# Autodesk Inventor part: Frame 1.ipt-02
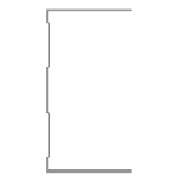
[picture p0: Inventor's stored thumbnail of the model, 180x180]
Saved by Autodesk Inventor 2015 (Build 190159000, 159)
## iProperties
IsCustomPart: 1
Created: 2015-04
Part Number: Frame 1.ipt-02
Material: Aluminum 6061
Description: Kévin Novo
Document SubType Name: Modeling
Standard: Kevin
Designer: suporte
Standards Organization: Kevin
Language: en-US
Size Designation: (Unnamed 2)
Categories: <MemberInstance><Categories><Category DisplayName="Structural Shapes" InternalName="089c4875-fa83-4c05-b084-43b9cc11f5ed" Mnemonic="GRDR"><CategoryParameter Dis
Density: 2.7 g/cm^3
Appearance: Aluminum - Flat
_CCFamilyMember: 2
_CCFamilyDisplayName: Kévin - Kévin Novo
_FrameMemberDoc: Frame Member File
_Version: 15.0.0
_GetPNFromCC: 1
G_W: 50,000 mm
G_H: 75,000 mm
G_L: 224,820 mm
+BD433694-75ED-40FA-B604-0D23CBD579F9+CUTDETAIL1: Miter 67,49 deg
Author: suporte
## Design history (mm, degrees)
node "Start Plane"
node "End Plane"
sketch "Sketch"
  geometry: L1 (24.7, 37.5)-(24.7, 36.9); L2 (24.7, 36.9)-(-24.7, 36.9); L3 (-24.7, -36.9)-(24.7, -36.9); L4 (24.7, -36.9)-(24.7, -37.5); L5 (24.7, -37.5)-(-25.3, -37.5); L6 (-25.3, 37.5)-(24.7, 37.5); L7 (-24.7, 36.9)-(-24.7, 31.9); L8 (-24.7, 31.9)-(-23.3, 30.5); L9 (-23.3, 30.5)-(-23.3, 10.934); L10 (-23.3, 10.934)-(-24.7, 9.534); L11 (-24.7, 9.534)-(-24.7, -9.534); L12 (-24.7, -9.534)-(-23.3, -10.934); L13 (-23.3, -10.934)-(-23.3, -30.5); L14 (-23.3, -30.5)-(-24.7, -31.9); L15 (-24.7, -31.9)-(-24.7, -36.9); L16 (-25.3, -37.5)-(-25.3, -31.651); L17 (-25.3, -31.651)-(-23.9, -30.251); L18 (-23.9, -30.251)-(-23.9, -11.183); L19 (-23.9, -11.183)-(-25.3, -9.783); L20 (-25.3, -9.783)-(-25.3, 9.783); L21 (-25.3, 9.783)-(-23.9, 11.183); L22 (-23.9, 11.183)-(-23.9, 30.251); L23 (-23.9, 30.251)-(-25.3, 31.651); L24 (-25.3, 31.651)-(-25.3, 37.5); L25 (-25.3, 0)-(30.37, 0); 3 further points
  constraints: 50 end point, 10 point on line, 9 parallel, 5 perpendicular, 4 equal length, 3 midpoint, 3 vertical, 2 vertical alignment, 1 collinear, 1 horizontal, 1 horizontal alignment
  dimensions: "d3" = 0.6 distance of L1.start L1.end (= d6); "d5" = 75 distance between parallel lines of L5 L6; "d6" = 0.6 distance between parallel lines of L24 L7 (= d8); "d7" = 0.6 distance between parallel lines of L8 L23 (= d8); "d8" = 0.6 distance between parallel lines of L22 L9 (= d12); "Espessura" = 0.6 distance between parallel lines of L17 L14; "d10" = 0.6 distance between parallel lines of L13 L18 (= Espessura); "d11" = 0.6 distance between parallel lines of L12 L19 (= Espessura); "d12" = 0.6 distance between parallel lines of L21 L10 (= d11); "d13" = 5 distance of L2.end L7.end; "d15" = 135 deg angle of L9 L8; "d16" = 2 distance between parallel lines of L24 L9; "d17" = 50 distance of L6.start L1.start
extrude "Body" join sketch "Sketch" stored distance "d24" = 0.13; taper "d25" = 0 deg
node "Driven Length"
  sketch "Sketch10"
    geometry: L1 (0, 0)-(10, 0) reference
    constraints: 2 end point, 1 horizontal
  workplane "Work Plane7"
  sketch "Sketch11"
    geometry: L1 (-2, 0)-(12, 0) reference; L2 (-2, 224.82)-(12, 224.82) reference
    dimensions: "d27" = 224.81978 distance between parallel lines of L1 L2 (derived)
workplane "Work Plane8"
split "Split1"
body "Solid1"
other parameters: "tamanho" = 188.55826, "G_OFFSET_START" = 0 [user parameter; used in 1 equation term], "G_OFFSET_END" = 36.26152 [user parameter; used in 1 equation term], "d22" = 0 (computed from G_OFFSET_START), "d23" = 224.81978 (= tamanho + G_OFFSET_END), "G_L" = 224.81978 (= d27) [user parameter], "d34" = 90 deg
